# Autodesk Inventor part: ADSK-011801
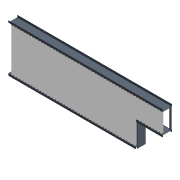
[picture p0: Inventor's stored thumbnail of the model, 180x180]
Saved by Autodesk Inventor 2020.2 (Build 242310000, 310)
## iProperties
Created: 2000-01
Part Number: ADSK-011801
Document SubType Name: Modeling
Designer: cmcgourin
Material: Plomb
Density: 11.37 g/cm^3
Appearance: Métal - Plomb
Mass: 855217 g
Surface Area: 92675.1 cm^2
Volume: 75217 cm^3
Control State: 0
Checked Out: False
Master: False
Shininess: 10.0
Length Units: 11269
Angle Units: 11279
Time Units: 11290
Mass Units: 11283
Length Display Precision: 3
Angle Display Precision: 2
Compacted: True
Dimensions: 915x184x2960 mm
Mass: 855,217 kg
DocNumber: ADSK-011801.ipt
Folder: 01 - Themengebiete\Simplification\01 - Packaging machine\
VDS_Category: 3D Komponenten
VLT_Material: Lead
Density: 11.37
Volumn: 76420.8590757843
Area: 90513.80305128386
PropertySet Name: Model Information
Author: cmcgourin
Revision Number: -
Title: roller conveyor
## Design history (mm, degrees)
node "Solide1"
node "Corps solides"
node "Corps surfaciques"
node "Extrusion1" dims "d0" = 178, "d1" = 0
node "Extrusion2" dims "d5" = 177.8, "d6" = 0
node "Mirror1"
node "Extrusion3" dims "d11" = 520.7, "d12" = 0
node "Shell1" dims "d13" = 3
node "Extrusion4" dims "d18" = 508, "d19" = 0
node "Extrusion5" dims "d24" = 508, "d25" = 0
node "Extrusion6" dims "d27" = 492.125, "d28" = 0
node "Extrusion7" dims "d32" = 381, "d33" = 0
chamfer "Fase1" distance "d67" = 3; stored, may be unused: second distance "d68" = 2, angle "d69" = 45 deg
node "Rectangular Pattern1" dims "d34" = 90, "d36" = 57
node "Extrusion8" dims "d40" = 838.2, "d41" = 0
chamfer "Fase2" distance "d71" = 3; stored, may be unused: second distance "d72" = 2, angle "d73" = 45 deg
node "Rectangular Pattern2" dims "d42" = 420, "d44" = 57
node "Extrusion9" dims "d55" = 495.3, "d56" = 0
fillet "Rundung1" dims "d64" = 6, "d65" = 3
sketch "Skizze11"
  geometry: L1 (1060, 439)-(-727, 439); L2 (-727, 439)-(-727, -439); L3 (-727, -439)-(1060, -439); L4 (1060, -439)-(1060, 439); L5 (1480, 419.5)-(1480, -419.5) reference; 7 further points
  constraints: 8 end point, 4 point on line, 2 midpoint, 2 parallel, 1 horizontal, 1 horizontal alignment, 1 perpendicular
  dimensions: "d74" = 420 distance between parallel lines of L5 L4; "d75" = 1787 distance of L2.end L3.end; "d76" = 878 distance of L1.end L2.end; "d77" = 82 distance from line of L2 point (-645, -439); "d78" = 82 distance from line of L4 point (978, -439) (= d77); "d79" = 82 distance from line of L2 point (-645, 439) (= d77); "d80" = 82.99995 distance from line of point (977, 439) L4
hole "Bohrung1" sketch "Skizze11" diameter "d81" = 13.5; stored, may be unused: countersink angle "d85" = 90 deg, drill point angle "d87" = 118 deg; dims "d82" = 6, "d83" = 20, "d84" = 13, "d86" = 8
node "Direktbearbeitung1"
sketch "Sketch1"
  geometry: L1 (-1480, -457.5)-(960, -457.5); L2 (-1480, 457.5)-(-1480, -457.5); L3 (1480, 457.5)-(-1480, 457.5); L4 (1480, -2.5)-(1480, 457.5); L5 (960, -2.5)-(1480, -2.5); L6 (960, -457.5)-(960, -2.5); 3 further points
  constraints: 12 end point, 2 midpoint, 2 perpendicular, 1 horizontal, 1 horizontal alignment, 1 parallel, 1 vertical alignment
  dimensions: "d45" = 2440 distance between parallel lines of L6 L2; "d46" = 2960 distance of L3.start L2.start; "d57" = 460 distance of L4.start L3.start; "d58" = 520 distance of L5.start L4.start; "d59" = 915 distance of L2.start L1.start
sketch "Sketch2"
  geometry: L1 (0, 0)-(178, 0) reference; L2 (175, 915)-(175, 880); L3 (175, 880)-(3, 880); L4 (3, 880)-(3, 915); L5 (0, 915)-(178, 915) reference; 2 further points
  constraints: 6 end point, 2 midpoint, 2 perpendicular, 2 point on line, 1 parallel, 1 vertical alignment
  dimensions: "d2" = 35 distance of L2.start L2.end; "d60" = 172 distance of L2.end L3.end
sketch "Sketch3"
  geometry: L1 (-3, 425)-(-175, 425) reference; L2 (-175, 0)-(-175, 35); L3 (-175, 35)-(-3, 35); L4 (-3, 35)-(-3, 0); L5 (-3, -420)-(-3, -455) reference; L6 (0, -455)-(-3, -455) reference; L7 (0, -455)-(0, 0) reference; L8 (0, 0)-(-178, 0) reference; L9 (-178, 0)-(-178, -455) reference; L10 (-175, -455)-(-178, -455) reference; L11 (-175, -455)-(-175, -420) reference; L12 (-175, -420)-(-3, -420) reference; L13 (0, 0)-(-178, 0) reference; 2 further points
  constraints: 6 end point, 2 midpoint, 2 perpendicular, 2 point on line, 1 parallel, 1 vertical alignment
  dimensions: "d61" = 172 distance of L2.end L3.end (= d60); "d62" = 35 distance of L2.start L2.end (= d2)
sketch "Sketch4"
  geometry: L1 (2954, 0)-(2941, 0); L2 (2935, 6)-(2935, 19); L3 (2941, 25)-(2954, 25); L4 (2960, 19)-(2960, 6); L5 (2941, 22)-(2954, 22); L6 (2957, 19)-(2957, 6); L7 (2954, 3)-(2941, 3); L8 (2938, 6)-(2938, 19); L9 (2960, 178)-(2960, 0) reference; L10 (2440, 0)-(2960, 0) reference; A1 r 6 centre (2941, 19) between (2941, 25) and (2935, 19); A2 r 6 centre (2954, 19) between (2960, 19) and (2954, 25); A3 r 6 centre (2941, 6) between (2935, 6) and (2941, 0); A4 r 6 centre (2954, 6) between (2954, 0) and (2960, 6); A5 r 3 centre (2941, 19) between (2941, 22) and (2938, 19); A6 r 3 centre (2954, 19) between (2957, 19) and (2954, 22); A7 r 3 centre (2954, 6) between (2954, 3) and (2957, 6); A8 r 3 centre (2941, 6) between (2938, 6) and (2941, 3); 3 further points
  constraints: 16 end point, 16 point on circle, 16 tangent, 8 centre point, 6 point on line, 4 parallel, 3 equal radius, 2 perpendicular, 1 collinear, 1 horizontal, 7 other
  dimensions: "d14" = 25 distance of point (2935, 25) point (2960, 25); "d15" = 25 distance of point (2935, 0) point (2935, 25) (= d14); "d16" = 6 radius of A1; "d17" = 3 distance between parallel lines of L2 L8; "d49" = 0 distance between parallel lines of L9 L4
sketch "Sketch5"
  geometry: L1 (6, -178)-(19, -178); L2 (25, -172)-(25, -159); L3 (19, -153)-(6, -153); L4 (0, -159)-(0, -172); L5 (3, -159)-(3, -172); L6 (6, -175)-(19, -175); L7 (22, -172)-(22, -159); L8 (19, -156)-(6, -156); L9 (0, -178)-(2440, -178) reference; L10 (0, 0)-(0, -178) reference; A1 r 6 centre (19, -159) between (25, -159) and (19, -153); A2 r 6 centre (19, -172) between (19, -178) and (25, -172); A3 r 6 centre (6, -172) between (0, -172) and (6, -178); A4 r 6 centre (6, -159) between (6, -153) and (0, -159); A5 r 3 centre (6, -159) between (6, -156) and (3, -159); A6 r 3 centre (6, -172) between (3, -172) and (6, -175); A7 r 3 centre (19, -172) between (19, -175) and (22, -172); A8 r 3 centre (19, -159) between (22, -159) and (19, -156); 3 further points
  constraints: 16 end point, 16 point on circle, 16 tangent, 8 centre point, 6 point on line, 4 parallel, 3 equal radius, 2 collinear, 2 perpendicular, 1 horizontal, 7 other
  dimensions: "d20" = 25 distance of point (25, -153) point (0, -153) (= d21); "d21" = 25 distance of point (25, -178) point (25, -153); "d22" = 6 radius of A1; "d23" = 3 distance between parallel lines of L3 L8
sketch "Sketch6"
  geometry: L1 (520, 0)-(0, 0) reference; L2 (60.325, -3)-(60.325, 175); L3 (60.325, -3)-(0, -3); L4 (0, 171.45)-(0, 0) reference; L5 (60.325, 175)-(41.275, 175); L6 (0, 0)-(0, 171.45) reference; L7 (50.8, 175)-(50.8, -3); 4 further points; 2 other entities
  constraints: 8 end point, 3 point on line, 1 midpoint, 1 parallel, 1 vertical, 4 other
  dimensions: "d52" = 9.525 distance between parallel lines of L2 L7; "d53" = 50.8 distance between parallel lines of L7 L4
sketch "Sketch7"
  geometry: L1 (0, 0)-(2960, 0) reference; C1 r 24 at (2922, -18); 1 further point
  constraints: 1 centre point, 1 other
  dimensions: "d29" = 48 diameter of C1; "d30" = 38 dimension on C1.centre; "d31" = 18 distance from line of L1 C1.centre
sketch "Sketch8"
  geometry: C1 r 24 at (-31, -18); C2 r 24 at (26, -18) reference
  constraints: 1 centre point, 1 horizontal alignment
  dimensions: "d37" = 48 diameter of C1; "d70" = 57 distance of C1.centre C2.centre
sketch "Sketch9"
  geometry: L1 (-520, 0)-(-520, 172) reference; L2 (-520, -3)-(0, -3) reference; L3 (-520, 175)-(-510, 175); L4 (-510, 175)-(-510, -3); L5 (-510, -3)-(-520, -3); L6 (-520, -3)-(-520, 175)
  constraints: 8 end point, 2 parallel, 1 horizontal, 1 perpendicular, 1 point on line
  dimensions: "d54" = 10 distance between parallel lines of L4 L1
node "Projizierte Kontur1"
node "Volumenkörper2"
node "Volumenkörper3"
node "Volumenkörper4"
node "Volumenkörper5"
node "Volumenkörper6"
feature "Verschieben2" dims "d93" = -10
feature "Verschieben3" dims "d96" = 3
feature "Verschieben4" dims "d99" = -25
other parameters: "d91" = 0, "d92" = 0, "d94" = 0, "d95" = 0, "d97" = 0, "d98" = 0
